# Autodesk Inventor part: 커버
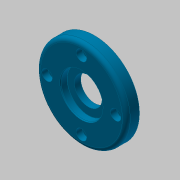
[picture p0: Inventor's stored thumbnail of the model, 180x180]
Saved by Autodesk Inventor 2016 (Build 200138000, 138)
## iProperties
Created: 2016-06
Part Number: 커버
Material: 알루미늄 6061
Document SubType Name: Modeling
Designer: mduedu
Density: 2.71 g/cm^3
Appearance: 하늘색 중간
Author: mduedu
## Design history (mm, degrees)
sketch "스케치1"
  geometry: C1 r 34 at (0, 0); 1 further point
  constraints: 1 centre point, 1 coincident
  dimensions: "d0" = 68 diameter of C1
extrude "돌출1" new body sketch "스케치1" distance "d2" = 10; taper "d3" = 0 deg
sketch "스케치2"
  geometry: C1 r 21 at (0, 0); 1 further point
  constraints: 1 centre point, 1 coincident
  dimensions: "d4" = 42 diameter of C1
extrude "돌출2" join sketch "스케치2" distance "d6" = 3; taper "d7" = 0 deg
fillet "모깎기1" dims "d8" = 3
hole "구멍1" diameter "d11" = 35; stored, may be unused: countersink angle "d15" = 90 deg, drill point angle "d17" = 0 deg; dims "d9" = 10, "d10" = 10, "d12" = 6, "d13" = 4, "d14" = 2, "d16" = 3
hole "구멍2" diameter "d20" = 32; stored, may be unused: countersink angle "d24" = 90 deg, drill point angle "d26" = 0 deg; dims "d21" = 6, "d22" = 4, "d23" = 2, "d25" = 5.2, "d46" = 10, "d47" = 10
hole "구멍3" diameter "d29" = 21; stored, may be unused: countersink angle "d33" = 90 deg, drill point angle "d35" = 0 deg; dims "d27" = 10, "d28" = 10, "d30" = 6, "d31" = 4, "d32" = 2, "d34" = 5
fillet "모깎기2" dims "d36" = 3
fillet "모깎기3" dims "d37" = 0.1
chamfer "모따기1" distance "d38" = 0.75; stored, may be unused: second distance "d39" = 2, angle "d40" = 30 deg
chamfer "모따기2" distance "d42" = 0.5; stored, may be unused: second distance "d43" = 2, angle "d44" = 30 deg
sketch "스케치3" dims "d48" = 52
  geometry: 6 further points
  constraints: 2 vertical alignment, 1 coincident, 7 other
  dimensions: "d51" = 360 deg dimension on point (0, 0) point (0, 26) (derived)
sketch "스케치4"
  geometry: 4 further points
hole "구멍4" sketch "스케치4" at (0, 26), (-26, 0), (0, -26), (26, 0) diameter "d53" = 4.5; stored, may be unused: countersink angle "d57" = 90 deg, drill point angle "d59" = 0 deg; dims "d54" = 6, "d55" = 8, "d56" = 4.6, "d58" = 8
node "솔리드1"
